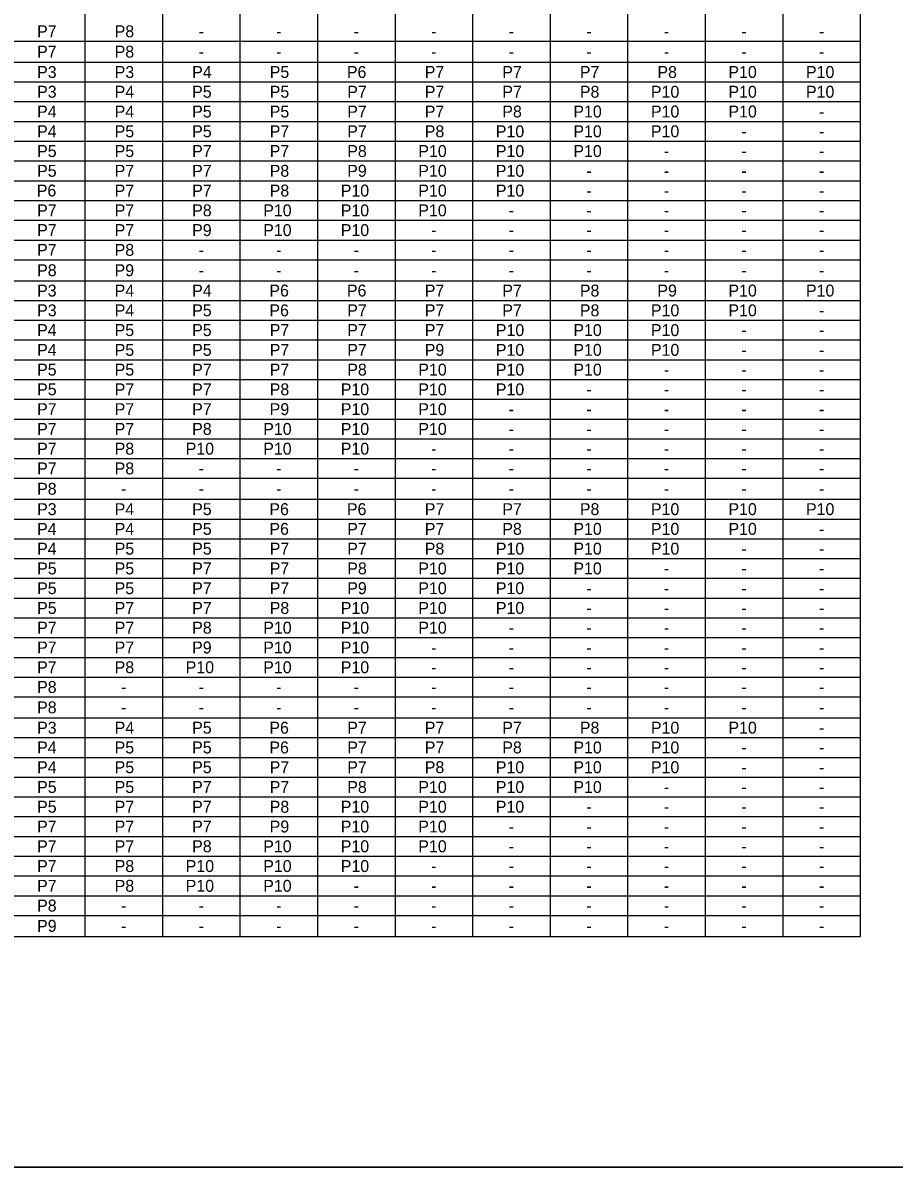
# Model space of a CAD drawing. Extents: x 637580 to 641008, y 294594 to 295782.
# Drawn here: x 639502.8 to 639722, y 295202.6 to 295490.5 of the extents above; entities that cross this region are included whole.
import ezdxf

# ---------------------------------------------------------------- set-up
doc = ezdxf.new("R2010")
doc.units = 0
doc.layers.add('1', color=7, linetype='Continuous')
doc.layers.add('2', color=7, linetype='Continuous')

msp = doc.modelspace()

# ---------------------------------------------------------------- linework, layer by layer
at = {"layer": '1'}
for p, q in [((639713.6, 295260.68), (639713.6, 295724.98)), ((639346.67, 295480.64), (639713.6, 295480.64)), ((639346.67, 295425.65), (639713.6, 295425.65)), ((639346.67, 295370.66), (639713.6, 295370.66)), ((639346.67, 295315.67), (639713.6, 295315.67)), ((639346.67, 295260.68), (639713.6, 295260.68)), ((640088.31, 295202.63), (639302.31, 295202.63)), ((639302.31, 295202.63), (639888.31, 295202.63))]:
    msp.add_line(p, q, dxfattribs=at)
at = {"layer": '2'}
for p, q in [((639518.52, 295260.68), (639518.52, 295709.96)), ((639538.03, 295260.68), (639538.03, 295709.96)), ((639557.54, 295260.68), (639557.54, 295709.96)), ((639577.04, 295260.68), (639577.04, 295709.96)), ((639596.55, 295260.68), (639596.55, 295709.96)), ((639616.06, 295260.68), (639616.06, 295709.96)), ((639635.57, 295260.68), (639635.57, 295709.96)), ((639655.07, 295260.68), (639655.07, 295709.96)), ((639674.58, 295260.68), (639674.58, 295709.96)), ((639694.09, 295260.68), (639694.09, 295709.96)), ((639373.47, 295485.9), (639713.6, 295485.9)), ((639373.47, 295475.66), (639713.6, 295475.66)), ((639373.47, 295470.69), (639713.6, 295470.69)), ((639373.47, 295465.72), (639713.6, 295465.72)), ((639373.47, 295460.75), (639713.6, 295460.75)), ((639373.47, 295455.77), (639713.6, 295455.77)), ((639373.47, 295450.8), (639713.6, 295450.8)), ((639373.47, 295445.83), (639713.6, 295445.83)), ((639373.47, 295440.86), (639713.6, 295440.86)), ((639373.47, 295435.88), (639713.6, 295435.88)), ((639373.47, 295430.91), (639713.6, 295430.91)), ((639373.47, 295420.67), (639713.6, 295420.67)), ((639373.47, 295415.7), (639713.6, 295415.7)), ((639373.47, 295410.73), (639713.6, 295410.73)), ((639373.47, 295405.76), (639713.6, 295405.76)), ((639373.47, 295400.78), (639713.6, 295400.78)), ((639373.47, 295395.81), (639713.6, 295395.81)), ((639373.47, 295390.84), (639713.6, 295390.84)), ((639373.47, 295385.87), (639713.6, 295385.87)), ((639373.47, 295380.89), (639713.6, 295380.89)), ((639373.47, 295375.92), (639713.6, 295375.92)), ((639373.47, 295365.68), (639713.6, 295365.68)), ((639373.47, 295360.71), (639713.6, 295360.71)), ((639373.47, 295355.74), (639713.6, 295355.74)), ((639373.47, 295350.77), (639713.6, 295350.77)), ((639373.47, 295345.79), (639713.6, 295345.79)), ((639373.47, 295340.82), (639713.6, 295340.82)), ((639373.47, 295335.85), (639713.6, 295335.85)), ((639373.47, 295330.88), (639713.6, 295330.88)), ((639373.47, 295325.9), (639713.6, 295325.9)), ((639373.47, 295320.93), (639713.6, 295320.93)), ((639373.47, 295310.69), (639713.6, 295310.69)), ((639373.47, 295305.72), (639713.6, 295305.72)), ((639373.47, 295300.75), (639713.6, 295300.75)), ((639373.47, 295295.78), (639713.6, 295295.78)), ((639373.47, 295290.8), (639713.6, 295290.8)), ((639373.47, 295285.83), (639713.6, 295285.83)), ((639373.47, 295280.86), (639713.6, 295280.86)), ((639373.47, 295275.89), (639713.6, 295275.89)), ((639373.47, 295270.91), (639713.6, 295270.91)), ((639373.47, 295265.94), (639713.6, 295265.94))]:
    msp.add_line(p, q, dxfattribs=at)

# ---------------------------------------------------------------- texts
at = {"layer": '1'}
for s, p in [('P7', (639506.42, 295486.89)), ('P8', (639525.93, 295486.89)), ('-', (639547.05, 295486.89)), ('-', (639566.56, 295486.89)), ('-', (639586.07, 295486.89)), ('-', (639605.57, 295486.89)), ('-', (639625.08, 295486.89)), ('-', (639644.59, 295486.89)), ('-', (639664.1, 295486.89)), ('-', (639683.6, 295486.89)), ('-', (639703.11, 295486.89)), ('P7', (639506.42, 295481.77)), ('P8', (639525.93, 295481.77)), ('-', (639547.05, 295481.77)), ('-', (639566.56, 295481.77)), ('-', (639586.07, 295481.77)), ('-', (639605.57, 295481.77)), ('-', (639625.08, 295481.77)), ('-', (639644.59, 295481.77)), ('-', (639664.1, 295481.77)), ('-', (639683.6, 295481.77)), ('-', (639703.11, 295481.77)), ('P3', (639506.42, 295476.65)), ('P3', (639525.93, 295476.65)), ('P4', (639545.43, 295476.65)), ('P5', (639564.94, 295476.65)), ('P6', (639584.36, 295476.65)), ('P7', (639603.95, 295476.65)), ('P7', (639623.46, 295476.65)), ('P7', (639642.97, 295476.65)), ('P8', (639662.48, 295476.65)), ('P10', (639680.35, 295476.65)), ('P10', (639699.86, 295476.65)), ('P3', (639506.42, 295471.68)), ('P4', (639525.93, 295471.68)), ('P5', (639545.43, 295471.68)), ('P5', (639564.94, 295471.68)), ('P7', (639584.45, 295471.68)), ('P7', (639603.95, 295471.68)), ('P7', (639623.46, 295471.68)), ('P8', (639642.97, 295471.68)), ('P10', (639660.85, 295471.68)), ('P10', (639680.35, 295471.68)), ('P10', (639699.86, 295471.68)), ('P4', (639506.42, 295466.71)), ('P4', (639525.93, 295466.71)), ('P5', (639545.43, 295466.71)), ('P5', (639564.94, 295466.71)), ('P7', (639584.45, 295466.71)), ('P7', (639603.95, 295466.71)), ('P8', (639623.46, 295466.71)), ('P10', (639641.34, 295466.71)), ('P10', (639660.85, 295466.71)), ('P10', (639680.35, 295466.71)), ('-', (639703.11, 295466.71)), ('P4', (639506.42, 295461.73)), ('P5', (639525.93, 295461.73)), ('P5', (639545.43, 295461.73)), ('P7', (639564.94, 295461.73)), ('P7', (639584.45, 295461.73)), ('P8', (639603.95, 295461.73)), ('P10', (639621.83, 295461.73)), ('P10', (639641.34, 295461.73)), ('P10', (639660.85, 295461.73)), ('-', (639683.6, 295461.73)), ('-', (639703.11, 295461.73)), ('P5', (639506.42, 295456.76)), ('P5', (639525.93, 295456.76)), ('P7', (639545.43, 295456.76)), ('P7', (639564.94, 295456.76)), ('P8', (639584.45, 295456.76)), ('P10', (639602.33, 295456.76)), ('P10', (639621.83, 295456.76)), ('P10', (639641.34, 295456.76)), ('-', (639664.1, 295456.76)), ('-', (639683.6, 295456.76)), ('-', (639703.11, 295456.76)), ('P5', (639506.42, 295451.79)), ('P7', (639525.93, 295451.79)), ('P7', (639545.43, 295451.79)), ('P8', (639564.94, 295451.79)), ('P9', (639584.44, 295451.79)), ('P10', (639602.33, 295451.79)), ('P10', (639621.83, 295451.79)), ('-', (639644.59, 295451.79)), ('-', (639664.1, 295451.79)), ('-', (639683.6, 295451.79)), ('-', (639703.11, 295451.79)), ('P6', (639506.33, 295446.82)), ('P7', (639525.93, 295446.82)), ('P7', (639545.43, 295446.82)), ('P8', (639564.94, 295446.82)), ('P10', (639582.82, 295446.82)), ('P10', (639602.33, 295446.82)), ('P10', (639621.83, 295446.82)), ('-', (639644.59, 295446.82)), ('-', (639664.1, 295446.82)), ('-', (639683.6, 295446.82)), ('-', (639703.11, 295446.82)), ('P7', (639506.42, 295441.84)), ('P7', (639525.93, 295441.84)), ('P8', (639545.43, 295441.84)), ('P10', (639563.31, 295441.84)), ('P10', (639582.82, 295441.84)), ('P10', (639602.33, 295441.84)), ('-', (639625.08, 295441.84)), ('-', (639644.59, 295441.84)), ('-', (639664.1, 295441.84)), ('-', (639683.6, 295441.84)), ('-', (639703.11, 295441.84)), ('P7', (639506.42, 295436.87)), ('P7', (639525.93, 295436.87)), ('P9', (639545.42, 295436.87)), ('P10', (639563.31, 295436.87)), ('P10', (639582.82, 295436.87)), ('-', (639605.57, 295436.87)), ('-', (639625.08, 295436.87)), ('-', (639644.59, 295436.87)), ('-', (639664.1, 295436.87)), ('-', (639683.6, 295436.87)), ('-', (639703.11, 295436.87)), ('P7', (639506.42, 295431.9)), ('P8', (639525.93, 295431.9)), ('-', (639547.05, 295431.9)), ('-', (639566.56, 295431.9)), ('-', (639586.07, 295431.9)), ('-', (639605.57, 295431.9)), ('-', (639625.08, 295431.9)), ('-', (639644.59, 295431.9)), ('-', (639664.1, 295431.9)), ('-', (639683.6, 295431.9)), ('-', (639703.11, 295431.9)), ('P8', (639506.42, 295426.78)), ('P9', (639525.91, 295426.78)), ('-', (639547.05, 295426.78)), ('-', (639566.56, 295426.78)), ('-', (639586.07, 295426.78)), ('-', (639605.57, 295426.78)), ('-', (639625.08, 295426.78)), ('-', (639644.59, 295426.78)), ('-', (639664.1, 295426.78)), ('-', (639683.6, 295426.78)), ('-', (639703.11, 295426.78)), ('P3', (639506.42, 295421.66)), ('P4', (639525.93, 295421.66)), ('P4', (639545.43, 295421.66)), ('P6', (639564.86, 295421.66)), ('P6', (639584.36, 295421.66)), ('P7', (639603.95, 295421.66)), ('P7', (639623.46, 295421.66)), ('P8', (639642.97, 295421.66)), ('P9', (639662.47, 295421.66)), ('P10', (639680.35, 295421.66)), ('P10', (639699.86, 295421.66)), ('P3', (639506.42, 295416.69)), ('P4', (639525.93, 295416.69)), ('P5', (639545.43, 295416.69)), ('P6', (639564.86, 295416.69)), ('P7', (639584.45, 295416.69)), ('P7', (639603.95, 295416.69)), ('P7', (639623.46, 295416.69)), ('P8', (639642.97, 295416.69)), ('P10', (639660.85, 295416.69)), ('P10', (639680.35, 295416.69)), ('-', (639703.11, 295416.69)), ('P4', (639506.42, 295411.72)), ('P5', (639525.93, 295411.72)), ('P5', (639545.43, 295411.72)), ('P7', (639564.94, 295411.72)), ('P7', (639584.45, 295411.72)), ('P7', (639603.95, 295411.72)), ('P10', (639621.83, 295411.72)), ('P10', (639641.34, 295411.72)), ('P10', (639660.85, 295411.72)), ('-', (639683.6, 295411.72)), ('-', (639703.11, 295411.72)), ('P4', (639506.42, 295406.74)), ('P5', (639525.93, 295406.74)), ('P5', (639545.43, 295406.74)), ('P7', (639564.94, 295406.74)), ('P7', (639584.45, 295406.74)), ('P9', (639603.94, 295406.74)), ('P10', (639621.83, 295406.74)), ('P10', (639641.34, 295406.74)), ('P10', (639660.85, 295406.74)), ('-', (639683.6, 295406.74)), ('-', (639703.11, 295406.74)), ('P5', (639506.42, 295401.77)), ('P5', (639525.93, 295401.77)), ('P7', (639545.43, 295401.77)), ('P7', (639564.94, 295401.77)), ('P8', (639584.45, 295401.77)), ('P10', (639602.33, 295401.77)), ('P10', (639621.83, 295401.77)), ('P10', (639641.34, 295401.77)), ('-', (639664.1, 295401.77)), ('-', (639683.6, 295401.77)), ('-', (639703.11, 295401.77)), ('P5', (639506.42, 295396.8)), ('P7', (639525.93, 295396.8)), ('P7', (639545.43, 295396.8)), ('P8', (639564.94, 295396.8)), ('P10', (639582.82, 295396.8)), ('P10', (639602.33, 295396.8)), ('P10', (639621.83, 295396.8)), ('-', (639644.59, 295396.8)), ('-', (639664.1, 295396.8)), ('-', (639683.6, 295396.8)), ('-', (639703.11, 295396.8)), ('P7', (639506.42, 295391.83)), ('P7', (639525.93, 295391.83)), ('P7', (639545.43, 295391.83)), ('P9', (639564.93, 295391.83)), ('P10', (639582.82, 295391.83)), ('P10', (639602.33, 295391.83)), ('-', (639625.08, 295391.83)), ('-', (639644.59, 295391.83)), ('-', (639664.1, 295391.83)), ('-', (639683.6, 295391.83)), ('-', (639703.11, 295391.83)), ('P7', (639506.42, 295386.85)), ('P7', (639525.93, 295386.85)), ('P8', (639545.43, 295386.85)), ('P10', (639563.31, 295386.85)), ('P10', (639582.82, 295386.85)), ('P10', (639602.33, 295386.85)), ('-', (639625.08, 295386.85)), ('-', (639644.59, 295386.85)), ('-', (639664.1, 295386.85)), ('-', (639683.6, 295386.85)), ('-', (639703.11, 295386.85)), ('P7', (639506.42, 295381.88)), ('P8', (639525.93, 295381.88)), ('P10', (639543.8, 295381.88)), ('P10', (639563.31, 295381.88)), ('P10', (639582.82, 295381.88)), ('-', (639605.57, 295381.88)), ('-', (639625.08, 295381.88)), ('-', (639644.59, 295381.88)), ('-', (639664.1, 295381.88)), ('-', (639683.6, 295381.88)), ('-', (639703.11, 295381.88)), ('P7', (639506.42, 295376.91)), ('P8', (639525.93, 295376.91)), ('-', (639547.05, 295376.91)), ('-', (639566.56, 295376.91)), ('-', (639586.07, 295376.91)), ('-', (639605.57, 295376.91)), ('-', (639625.08, 295376.91)), ('-', (639644.59, 295376.91)), ('-', (639664.1, 295376.91)), ('-', (639683.6, 295376.91)), ('-', (639703.11, 295376.91)), ('P8', (639506.42, 295371.79)), ('-', (639527.54, 295371.79)), ('-', (639547.05, 295371.79)), ('-', (639566.56, 295371.79)), ('-', (639586.07, 295371.79)), ('-', (639605.57, 295371.79)), ('-', (639625.08, 295371.79)), ('-', (639644.59, 295371.79)), ('-', (639664.1, 295371.79)), ('-', (639683.6, 295371.79)), ('-', (639703.11, 295371.79)), ('P3', (639506.42, 295366.67)), ('P4', (639525.93, 295366.67)), ('P5', (639545.43, 295366.67)), ('P6', (639564.86, 295366.67)), ('P6', (639584.36, 295366.67)), ('P7', (639603.95, 295366.67)), ('P7', (639623.46, 295366.67)), ('P8', (639642.97, 295366.67)), ('P10', (639660.85, 295366.67)), ('P10', (639680.35, 295366.67)), ('P10', (639699.86, 295366.67)), ('P4', (639506.42, 295361.7)), ('P4', (639525.93, 295361.7)), ('P5', (639545.43, 295361.7)), ('P6', (639564.86, 295361.7)), ('P7', (639584.45, 295361.7)), ('P7', (639603.95, 295361.7)), ('P8', (639623.46, 295361.7)), ('P10', (639641.34, 295361.7)), ('P10', (639660.85, 295361.7)), ('P10', (639680.35, 295361.7)), ('-', (639703.11, 295361.7)), ('P4', (639506.42, 295356.73)), ('P5', (639525.93, 295356.73)), ('P5', (639545.43, 295356.73)), ('P7', (639564.94, 295356.73)), ('P7', (639584.45, 295356.73)), ('P8', (639603.95, 295356.73)), ('P10', (639621.83, 295356.73)), ('P10', (639641.34, 295356.73)), ('P10', (639660.85, 295356.73)), ('-', (639683.6, 295356.73)), ('-', (639703.11, 295356.73)), ('P5', (639506.42, 295351.75)), ('P5', (639525.93, 295351.75)), ('P7', (639545.43, 295351.75)), ('P7', (639564.94, 295351.75)), ('P8', (639584.45, 295351.75)), ('P10', (639602.33, 295351.75)), ('P10', (639621.83, 295351.75)), ('P10', (639641.34, 295351.75)), ('-', (639664.1, 295351.75)), ('-', (639683.6, 295351.75)), ('-', (639703.11, 295351.75)), ('P5', (639506.42, 295346.78)), ('P5', (639525.93, 295346.78)), ('P7', (639545.43, 295346.78)), ('P7', (639564.94, 295346.78)), ('P9', (639584.44, 295346.78)), ('P10', (639602.33, 295346.78)), ('P10', (639621.83, 295346.78)), ('-', (639644.59, 295346.78)), ('-', (639664.1, 295346.78)), ('-', (639683.6, 295346.78)), ('-', (639703.11, 295346.78)), ('P5', (639506.42, 295341.81)), ('P7', (639525.93, 295341.81)), ('P7', (639545.43, 295341.81)), ('P8', (639564.94, 295341.81)), ('P10', (639582.82, 295341.81)), ('P10', (639602.33, 295341.81)), ('P10', (639621.83, 295341.81)), ('-', (639644.59, 295341.81)), ('-', (639664.1, 295341.81)), ('-', (639683.6, 295341.81)), ('-', (639703.11, 295341.81)), ('P7', (639506.42, 295336.84)), ('P7', (639525.93, 295336.84)), ('P8', (639545.43, 295336.84)), ('P10', (639563.31, 295336.84)), ('P10', (639582.82, 295336.84)), ('P10', (639602.33, 295336.84)), ('-', (639625.08, 295336.84)), ('-', (639644.59, 295336.84)), ('-', (639664.1, 295336.84)), ('-', (639683.6, 295336.84)), ('-', (639703.11, 295336.84)), ('P7', (639506.42, 295331.86)), ('P7', (639525.93, 295331.86)), ('P9', (639545.42, 295331.86)), ('P10', (639563.31, 295331.86)), ('P10', (639582.82, 295331.86)), ('-', (639605.57, 295331.86)), ('-', (639625.08, 295331.86)), ('-', (639644.59, 295331.86)), ('-', (639664.1, 295331.86)), ('-', (639683.6, 295331.86)), ('-', (639703.11, 295331.86)), ('P7', (639506.42, 295326.89)), ('P8', (639525.93, 295326.89)), ('P10', (639543.8, 295326.89)), ('P10', (639563.31, 295326.89)), ('P10', (639582.82, 295326.89)), ('-', (639605.57, 295326.89)), ('-', (639625.08, 295326.89)), ('-', (639644.59, 295326.89)), ('-', (639664.1, 295326.89)), ('-', (639683.6, 295326.89)), ('-', (639703.11, 295326.89)), ('P8', (639506.42, 295321.92)), ('-', (639527.54, 295321.92)), ('-', (639547.05, 295321.92)), ('-', (639566.56, 295321.92)), ('-', (639586.07, 295321.92)), ('-', (639605.57, 295321.92)), ('-', (639625.08, 295321.92)), ('-', (639644.59, 295321.92)), ('-', (639664.1, 295321.92)), ('-', (639683.6, 295321.92)), ('-', (639703.11, 295321.92)), ('P8', (639506.42, 295316.8)), ('-', (639527.54, 295316.8)), ('-', (639547.05, 295316.8)), ('-', (639566.56, 295316.8)), ('-', (639586.07, 295316.8)), ('-', (639605.57, 295316.8)), ('-', (639625.08, 295316.8)), ('-', (639644.59, 295316.8)), ('-', (639664.1, 295316.8)), ('-', (639683.6, 295316.8)), ('-', (639703.11, 295316.8)), ('P3', (639506.42, 295311.68)), ('P4', (639525.93, 295311.68)), ('P5', (639545.43, 295311.68)), ('P6', (639564.86, 295311.68)), ('P7', (639584.45, 295311.68)), ('P7', (639603.95, 295311.68)), ('P7', (639623.46, 295311.68)), ('P8', (639642.97, 295311.68)), ('P10', (639660.85, 295311.68)), ('P10', (639680.35, 295311.68)), ('-', (639703.11, 295311.68)), ('P4', (639506.42, 295306.71)), ('P5', (639525.93, 295306.71)), ('P5', (639545.43, 295306.71)), ('P6', (639564.86, 295306.71)), ('P7', (639584.45, 295306.71)), ('P7', (639603.95, 295306.71)), ('P8', (639623.46, 295306.71)), ('P10', (639641.34, 295306.71)), ('P10', (639660.85, 295306.71)), ('-', (639683.6, 295306.71)), ('-', (639703.11, 295306.71)), ('P4', (639506.42, 295301.74)), ('P5', (639525.93, 295301.74)), ('P5', (639545.43, 295301.74)), ('P7', (639564.94, 295301.74)), ('P7', (639584.45, 295301.74)), ('P8', (639603.95, 295301.74)), ('P10', (639621.83, 295301.74)), ('P10', (639641.34, 295301.74)), ('P10', (639660.85, 295301.74)), ('-', (639683.6, 295301.74)), ('-', (639703.11, 295301.74)), ('P5', (639506.42, 295296.76)), ('P5', (639525.93, 295296.76)), ('P7', (639545.43, 295296.76)), ('P7', (639564.94, 295296.76)), ('P8', (639584.45, 295296.76)), ('P10', (639602.33, 295296.76)), ('P10', (639621.83, 295296.76)), ('P10', (639641.34, 295296.76)), ('-', (639664.1, 295296.76)), ('-', (639683.6, 295296.76)), ('-', (639703.11, 295296.76)), ('P5', (639506.42, 295291.79)), ('P7', (639525.93, 295291.79)), ('P7', (639545.43, 295291.79)), ('P8', (639564.94, 295291.79)), ('P10', (639582.82, 295291.79)), ('P10', (639602.33, 295291.79)), ('P10', (639621.83, 295291.79)), ('-', (639644.59, 295291.79)), ('-', (639664.1, 295291.79)), ('-', (639683.6, 295291.79)), ('-', (639703.11, 295291.79)), ('P7', (639506.42, 295286.82)), ('P7', (639525.93, 295286.82)), ('P7', (639545.43, 295286.82)), ('P9', (639564.93, 295286.82)), ('P10', (639582.82, 295286.82)), ('P10', (639602.33, 295286.82)), ('-', (639625.08, 295286.82)), ('-', (639644.59, 295286.82)), ('-', (639664.1, 295286.82)), ('-', (639683.6, 295286.82)), ('-', (639703.11, 295286.82)), ('P7', (639506.42, 295281.85)), ('P7', (639525.93, 295281.85)), ('P8', (639545.43, 295281.85)), ('P10', (639563.31, 295281.85)), ('P10', (639582.82, 295281.85)), ('P10', (639602.33, 295281.85)), ('-', (639625.08, 295281.85)), ('-', (639644.59, 295281.85)), ('-', (639664.1, 295281.85)), ('-', (639683.6, 295281.85)), ('-', (639703.11, 295281.85)), ('P7', (639506.42, 295276.87)), ('P8', (639525.93, 295276.87)), ('P10', (639543.8, 295276.87)), ('P10', (639563.31, 295276.87)), ('P10', (639582.82, 295276.87)), ('-', (639605.57, 295276.87)), ('-', (639625.08, 295276.87)), ('-', (639644.59, 295276.87)), ('-', (639664.1, 295276.87)), ('-', (639683.6, 295276.87)), ('-', (639703.11, 295276.87)), ('P7', (639506.42, 295271.9)), ('P8', (639525.93, 295271.9)), ('P10', (639543.8, 295271.9)), ('P10', (639563.31, 295271.9)), ('-', (639586.07, 295271.9)), ('-', (639605.57, 295271.9)), ('-', (639625.08, 295271.9)), ('-', (639644.59, 295271.9)), ('-', (639664.1, 295271.9)), ('-', (639683.6, 295271.9)), ('-', (639703.11, 295271.9)), ('P8', (639506.42, 295266.93)), ('-', (639527.54, 295266.93)), ('-', (639547.05, 295266.93)), ('-', (639566.56, 295266.93)), ('-', (639586.07, 295266.93)), ('-', (639605.57, 295266.93)), ('-', (639625.08, 295266.93)), ('-', (639644.59, 295266.93)), ('-', (639664.1, 295266.93)), ('-', (639683.6, 295266.93)), ('-', (639703.11, 295266.93)), ('P9', (639506.41, 295261.81)), ('-', (639527.54, 295261.81)), ('-', (639547.05, 295261.81)), ('-', (639566.56, 295261.81)), ('-', (639586.07, 295261.81)), ('-', (639605.57, 295261.81)), ('-', (639625.08, 295261.81)), ('-', (639644.59, 295261.81)), ('-', (639664.1, 295261.81)), ('-', (639683.6, 295261.81)), ('-', (639703.11, 295261.81))]:
    msp.add_text(s, height=3, dxfattribs=at).set_placement(p)

doc.saveas('drawing.dxf')
